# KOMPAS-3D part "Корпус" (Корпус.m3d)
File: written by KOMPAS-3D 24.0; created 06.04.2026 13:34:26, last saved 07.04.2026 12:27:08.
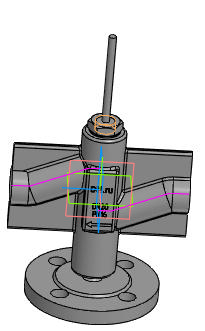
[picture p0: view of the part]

Document properties: Автор: R2D2; Полное имя файла: E:\Работа\Зайцев\Солянка\VSR1-13V-PED-F Клапан запорно-регулирующий DN.ru\DN20\исходные материалы\Корпус.m3d

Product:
- Body: Труба / Нестандартная труба / L = 73.6 мм  | qty 1
    Материал: Нестандартная труба (density 7856 kg/m3)
    Масса: 1.890403
    Раздел спецификации: Детали
    Примечание: 0,41 кг
    additional columns: Pipeline; 0.03; 0; 0; 0.002; 0.07364; true; 0.04
- Body: Труба / Нестандартная труба / L = 73.6 мм  | qty 1
    Материал: Нестандартная труба (density 7856 kg/m3)
    Масса: 1.890403
    Раздел спецификации: Детали
    Форматы листов документа: БЧ
    Примечание: 0,41 кг
    additional columns: Pipeline; 0.03; 0; 0; 0.002; 0.07364; true; 0.04
- Component [standard]: Гайка М16-6H ГОСТ 5916-70  | qty 1  | Масса: 0.01768; Рассекать на разрезах: no; source file: C:\Program Files\ASCON\KOMPAS-3D v24\Libs\PolynomLib\DATA\vault\Methods\Kompas\3D\PLib_Nut_OST92_900.m3d
- Component [standard]: Заглушка 20-16-B-1-ВЧ40-II ГОСТ 34785-2021  | qty 1  | Материал: ВЧ40 ГОСТ 7293-85 (density 7200 kg/m3); Масса: 0.737892; Рассекать на разрезах: no; source file: C:\Program Files\ASCON\KOMPAS-3D v24\Libs\PolynomLib\DATA\vault\Methods\Kompas\3D\PLib_Flange_Blind_GOST_34785_2100.m3d
- Body: Тело 4  | qty 1
    Материал: Нестандартная труба (density 7856 kg/m3)
    Масса: 1.890403
- Part/product: Корпус
    Масса: 6.9

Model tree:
1. Эскиз:1
2. Труба:1  (labels: {F703FF30-5BE6-4673-A7F1-8EDA1BE1E2D1}; SHAPEOBJECT3D_ATTR_BUTT; SHAPEOBJECT3D_ATTR_VALID; SHAPEOBJECT3D_ATTR_BUTT_AREA)
     PIPE_R = 7
3. Труба:2  (labels: {F703FF30-5BE6-4673-A7F1-8EDA1BE1E2D1}; SHAPEOBJECT3D_ATTR_BUTT; SHAPEOBJECT3D_ATTR_VALID; SHAPEOBJECT3D_ATTR_BUTT_AREA)
     PIPE_R = 7
4. Эскиз:2
5. Элемент выдавливания:1
     Расстояние 1 = 53; Смещение 1 = -1; Расстояние 2 = 71; Смещение 2 = -5
6. Эскиз:3  (with: Ребро.Труба:2)
7. Элемент выдавливания:2
     Расстояние 1 = 6
8. Эскиз:4  (with: Грань.Элемент выдавливания:1)
9. Элемент выдавливания:3
     Расстояние 1 = 1
10. Эскиз:5  (with: Грань.Элемент выдавливания:3)
11. Элемент выдавливания:4
     Расстояние 1 = 7.5; Смещение 1 = 0.5
12. ШТОК
13. Элемент выдавливания:5
14. Скругление:3  (with: Ребро.Элемент выдавливания:2)
     Радиус = 2
15. ОТЛИВКА
16. Скругление:6  (with: Грань.Элемент выдавливания:1)
     Радиус = 2
17. Элемент выдавливания:6  (with: Грань.Элемент выдавливания:1)
     Смещение 1 = 4
18. Эскиз:8  (with: Грань.Элемент выдавливания:6)
19. Элемент выдавливания:7
     Расстояние 1 = 0.5
20. Скругление:7  (with: Ребро.Элемент выдавливания:6)
     Радиус = 2
21. Скругление:8  (with: Ребро.Элемент выдавливания:6, Грань.Элемент выдавливания:3, Грань.Элемент выдавливания:1)
     Радиус = 2

Expressions: DS/2+3
Referenced files in C:\Program Files\ASCON\KOMPAS-3D v24\Libs\Pipeline\: StylesTemplate.a3d, TemplateHPH, InsulationStylesTemplate.a3d, Insulation
Referenced files in C:\Program Files\ASCON\KOMPAS-3D v24\Templates\: Констр. чертеж А3 гориз. перв. лист.cdt
Referenced files in E:\Работа\Зайцев\Солянка\VSR1-13V-PED-F Клапан запорно-регулирующий DN.ru\DN15\DN15 Kv0.16\исходные материалы\: 
Referenced files in C:\Program Files\ASCON\KOMPAS-3D v24\Libs\PolynomLib\DATA\vault\Methods\Kompas\3D\: PLib_Nut_OST92_900.m3d, PLib_Flange_Blind_GOST_34785_2100.m3d
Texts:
  Отводы ГОСТ 17375-2001
  Констр. чертеж А3 гориз. перв. лист.cdt
  BOSimple***PART:2c8e7818-1586-f79e-db7d-bc045ba468e4***SHORTLOC:Root±30±10±20±©{}110±10±50±80[Нет;Без покрытия;Без указания материала;-;16;2;24]
  BOSimple***Material:38d6725a-5efe-48e1-b177-a7817acb862a
  BOSimple***PART:e5a80285-45fa-e52f-3e72-d8f0ef91807d***SHORTLOC:B619_EF039B503CC34112[1;16;20;Круглая;II;ВЧ40 ГОСТ 7293-85]
  var3D
  GOST 2.304 type A
  PN16
  DN+10
  LL-10
  bcut1
  hole1
  hcut1
  hole2
  cut1
  Труба / Нестандартная труба / L = %s мм
  Plane. Начало координат
  Плоскость ZX.Начало координат
  Ось Y.Начало координат
  Плоскость ZY.Начало координат
  Горизонтальная плоскость. Начало координат
  Плоскость XY.Начало координат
